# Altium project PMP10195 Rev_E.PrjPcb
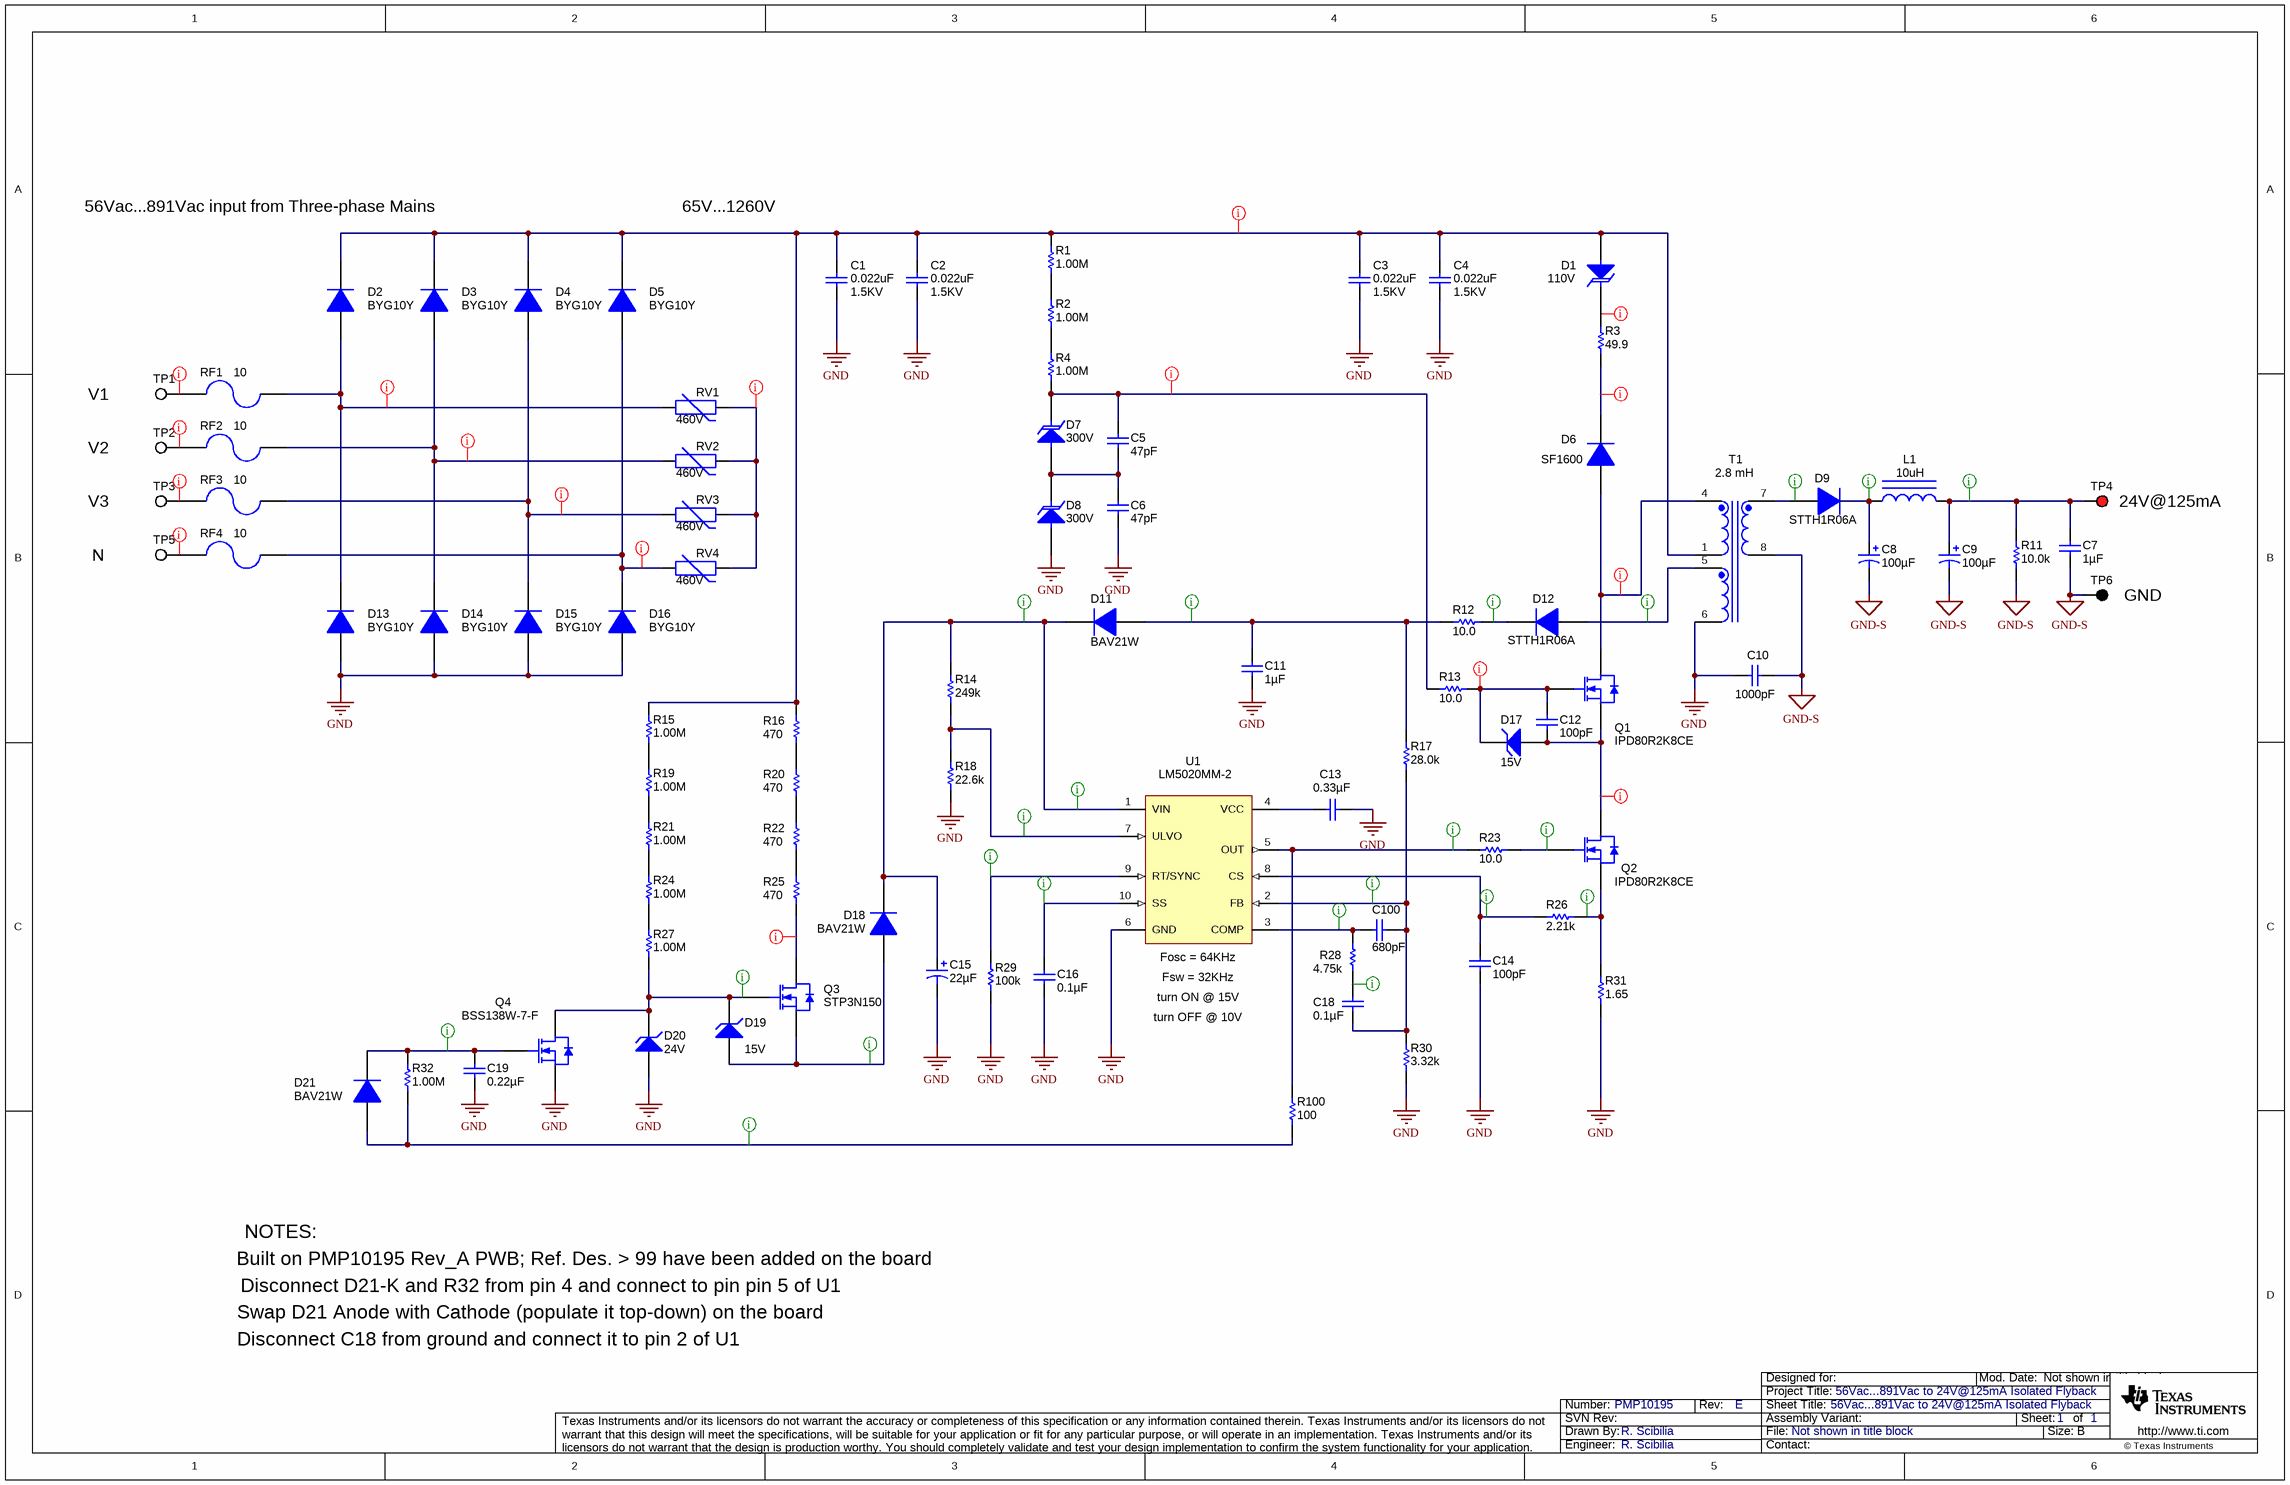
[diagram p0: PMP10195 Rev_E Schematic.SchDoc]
SCH_Rev: E; PRJ_Title: 56Vac...891Vac to 24V@125mA Isolated Flyback; PRJ_Number: PMP10195; PRJ_Engineer: R. Scibilia; PCB_Rev: A
1 sheet, 87 parts. Net scope: global (net labels, ports and power ports of the same name join across sheets).
Board file: PMP10195 Rev_A PCB.PcbDoc

## Sheet PMP10195 Rev_E Schematic.SchDoc: 56Vac...891Vac to 24V@125mA Isolated Flyback
size 431 x 279 mm; Date: Not shown in title block; ApprovedBy: Not shown in title block; CheckedBy: Not shown in title block; Author: Not shown in title block; CompanyName: Not shown in title block; DrawnBy: R. Scibilia; Engineer: R. Scibilia; Organization: Not shown in title block; Address1: Not shown in title block; Address2: Not shown in title block; Address3: Not shown in title block; Address4: Not shown in title block; DocumentNumber: 1; Revision: E; SheetNumber: 1; SheetTotal: 1; PageSetup: Record=PageOptions¦CenterHorizontal=True¦CenterVertical=True¦PrintScale=0.62¦XCorrection=1.00¦YCorrection=1.00¦PrintKind=0¦BorderSize=5000000¦LeftOffset=0¦BottomOffset=0¦Orientation=2¦PaperLength=1000¦PaperWidth=1000¦Scale=100¦PaperSource=15¦PrintQuality=600¦MediaType=1¦DitherType=10¦PaperKind=Letter¦PrintScaleMode=1

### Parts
C1  value 0.022uF  VDC_V: 1.5KV  [1210]  (hidden comment: C1210C223KFRACTU)
C2  value 0.022uF  VDC_V: 1.5KV  [1210]  (hidden comment: C1210C223KFRACTU)
C3  value 0.022uF  VDC_V: 1.5KV  [1210]  (hidden comment: C1210C223KFRACTU)
C4  value 0.022uF  VDC_V: 1.5KV  [1210]  (hidden comment: C1210C223KFRACTU)
C5  ValueDisplayed: 47pF  [1206]  (hidden comment: GRM31A7U3A470JW31D)
C6  ValueDisplayed: 47pF  [1206]  (hidden comment: GRM31A7U3A470JW31D)
C7  ValueDisplayed: 1µF  [0805_HV]  (hidden comment: C2012X7R1H105K125AB)
C8  ValueDisplayed: 100µF  [ZLJ_800X1150]  (hidden comment: 50ZLJ100MT78X11.5)
C9  ValueDisplayed: 100µF  [ZLJ_800X1150]  (hidden comment: 50ZLJ100MT78X11.5)
C10  value 1000pF  [1808]  (hidden comment: GA342DR7GF102KW02L)
C11  ValueDisplayed: 1µF  [0603]  (hidden comment: C1608X5R1E105K080AC)
C12  ValueDisplayed: 100pF  [0603]  (hidden comment: C1608C0G1H101J)
C13  ValueDisplayed: 0.33µF  [0603]  (hidden comment: C0603C334K4RACTU)
C14  ValueDisplayed: 100pF  [0603]  (hidden comment: C1608C0G1H101J)
C15  ValueDisplayed: 22µF  [SM_RADIAL_E]  (hidden comment: EEE-FC1H220P)
C16  ValueDisplayed: 0.1µF  [0603]  (hidden comment: C1608X7R1E104K)
C18  ValueDisplayed: 0.1µF  [0603]  (hidden comment: C1608X7R1E104K)
C19  ValueDisplayed: 0.22µF  [0603]  (hidden comment: C1608X7R1C224K)
C100  ValueDisplayed: 680pF  [0603]  (hidden comment: C1608C0G1H681J)
D1  value 110V  [SMA]  (hidden comment: SMAJ110A)
D2  BYG10Y  [SMA]
D3  BYG10Y  [SMA]
D4  BYG10Y  [SMA]
D5  BYG10Y  [SMA]
D6  SF1600  [DO-41]
D7  value 300V  [SMA]  (hidden comment: SMAJ300A)
D8  value 300V  [SMA]  (hidden comment: SMAJ300A)
D9  STTH1R06A  [SMA]
D11  value BAV21W  [SOD-123]  (hidden comment: BAV21W-7-F)
D12  STTH1R06A  [SMA]
D13  BYG10Y  [SMA]
D14  BYG10Y  [SMA]
D15  BYG10Y  [SMA]
D16  BYG10Y  [SMA]
D17  value 15V  [sod-323]  (hidden comment: MMSZ5245BS-7-F)
D18  value BAV21W  [SOD-123]  (hidden comment: BAV21W-7-F)
D19  value 15V  [sod-323]  (hidden comment: MMSZ5245BS-7-F)
D20  value 24V  [sod-323]  (hidden comment: MMSZ5252BS-7-F)
D21  value BAV21W  [SOD-123]  (hidden comment: BAV21W-7-F)
L1  value 10uH  [NLC453232T]  (hidden comment: NLC453232T-100K-PF)
Q1  IPD80R2K8CE  [DPAK]
Q2  IPD80R2K8CE  [DPAK]
Q3  STP3N150  [TO-220AB]
Q4  BSS138W-7-F  [SOT-323]
R1  ValueDisplayed: 1.00M  [1210M]  (hidden comment: ERJ14NF1004U)
R2  ValueDisplayed: 1.00M  [1210M]  (hidden comment: ERJ14NF1004U)
R3  ValueDisplayed: 49.9  [0603]  (hidden comment: CRCW060349R9FKEA)
R4  ValueDisplayed: 1.00M  [1210M]  (hidden comment: ERJ14NF1004U)
R11  ValueDisplayed: 10.0k  [0805_HV]  (hidden comment: CRCW080510K0FKEA)
R12  value 10.0  [0603]  (hidden comment: CRCW060310R0FKEA)
R13  value 10.0  [0603]  (hidden comment: CRCW060310R0FKEA)
R14  ValueDisplayed: 249k  [0603]  (hidden comment: CRCW0603249KFKEA)
R15  ValueDisplayed: 1.00M  [1210M]  (hidden comment: ERJ14NF1004U)
R16  ValueDisplayed: 470  [2010]  (hidden comment: CRCW2010470RJNEF)
R17  ValueDisplayed: 28.0k  [0603]  (hidden comment: CRCW060328K0FKEA)
R18  ValueDisplayed: 22.6k  [0603]  (hidden comment: CRCW060322K6FKEA)
R19  ValueDisplayed: 1.00M  [1210M]  (hidden comment: ERJ14NF1004U)
R20  ValueDisplayed: 470  [2010]  (hidden comment: CRCW2010470RJNEF)
R21  ValueDisplayed: 1.00M  [1210M]  (hidden comment: ERJ14NF1004U)
R22  ValueDisplayed: 470  [2010]  (hidden comment: CRCW2010470RJNEF)
R23  value 10.0  [0603]  (hidden comment: CRCW060310R0FKEA)
R24  ValueDisplayed: 1.00M  [1210M]  (hidden comment: ERJ14NF1004U)
R25  ValueDisplayed: 470  [2010]  (hidden comment: CRCW2010470RJNEF)
R26  ValueDisplayed: 2.21k  [0603]  (hidden comment: CRCW06032K21FKEA)
R27  ValueDisplayed: 1.00M  [1210M]  (hidden comment: ERJ14NF1004U)
R28  ValueDisplayed: 4.75k  [0603]  (hidden comment: CRCW06034K75FKEA)
R29  ValueDisplayed: 100k  [0603]  (hidden comment: CRCW0603100KFKEA)
R30  ValueDisplayed: 3.32k  [0603]  (hidden comment: CRCW06033K32FKEA)
R31  ValueDisplayed: 1.65  [0805_HV]  (hidden comment: CRCW08051R65FKEA)
R32  ValueDisplayed: 1.00M  [0603]  (hidden comment: CRCW06031M00FKEA)
R100  ValueDisplayed: 100  [0603]  (hidden comment: CRCW0603100RFKEA)
RF1  value 10  [RESAD1524W55L900D150]  (hidden comment: FKN1WSJR-52-10R)
RF2  value 10  [RESAD1524W55L900D150]  (hidden comment: FKN1WSJR-52-10R)
RF3  value 10  [RESAD1524W55L900D150]  (hidden comment: FKN1WSJR-52-10R)
RF4  value 10  [RESAD1524W55L900D150]  (hidden comment: FKN1WSJR-52-10R)
RV1  value 460V  [VAR_S07K300E2]  (hidden comment: B72205S0461K101)
RV2  value 460V  [VAR_S07K300E2]  (hidden comment: B72205S0461K101)
RV3  value 460V  [VAR_S07K300E2]  (hidden comment: B72205S0461K101)
RV4  value 460V  [VAR_S07K300E2]  (hidden comment: B72205S0461K101)
T1  value 2.8 mH  [GCI_EFD15R150-S525]  (hidden comment: EFD15R150-S525)
TP1  5002  [Keystone5002]  (value not drawn)
TP2  5002  [Keystone5002]  (value not drawn)
TP3  5002  [Keystone5002]  (value not drawn)
TP4  5000  [Keystone5000]  (value not drawn)
TP5  5002  [Keystone5002]  (value not drawn)
TP6  5001  [Keystone5001]  (value not drawn)
U1  LM5020MM-2  [MUB10A_N]

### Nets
GND: C1.2 C2.2 C3.2 C4.2 C6.2 C10.2 C11.2 C13.2 C14.2 C15.2(-) C16.2 C19.2 D8.2(A) D13.2(A) D14.2(A) D15.2(A) D16.2(A) D20.2(A) Q4.2(S) R18.1 R29.1 R30.1 R31.1 T1.6 U1.6(GND)
GND-S: C7.2 C8.2(-) C9.2(-) C10.1 R11.1 T1.8 TP6.1
NetC1_1: C1.1 C2.1 C3.1 C4.1 D1.2(A) D2.1(K) D3.1(K) D4.1(K) D5.1(K) R1.2 R15.2 R16.2 T1.1
NetC5_1: C5.1 D7.1(K) R4.1 R13.1
NetC5_2: C5.2 C6.1 D7.2(A) D8.1(K)
NetC7_1: C7.1 C9.1(+) L1.2 R11.2 TP4.1
NetC8_1: C8.1(+) D9.1(K) L1.1
NetC11_1: C11.1 D11.2(A) R12.2 R17.2
NetC12_1: C12.1 D17.1(K) Q1.1(G) R13.2
NetC12_2: C12.2 D17.2(A) Q1.3(S) Q2.4(D)
NetC13_1: C13.1 U1.4(VCC)
NetC14_1: C14.1 R26.1 U1.8(CS)
NetC15_1: C15.1(+) D11.1(K) D18.1(K) R14.2 U1.1(VIN)
NetC16_1: C16.1 U1.10(SS)
NetC18_1: C18.1 R28.1
NetC18_2: C18.2 C100.1 R17.1 R30.2 U1.2(FB)
NetC19_1: C19.1 D21.1(K) Q4.1(G) R32.2
NetC100_2: C100.2 R28.2 U1.3(COMP)
NetD1_1: D1.1(K) R3.2
NetD2_2: D2.2(A) D13.1(K) RF1.1 RV1.1
NetD3_2: D3.2(A) D14.1(K) RF2.1 RV2.1
NetD4_2: D4.2(A) D15.1(K) RF3.1 RV3.1
NetD5_2: D5.2(A) D16.1(K) RF4.1 RV4.1
NetD6_1: D6.1(K) R3.1
NetD6_2: D6.2(A) Q1.4(D) T1.4
NetD9_2: D9.2(A) T1.7
NetD12_1: D12.1(K) R12.1
NetD12_2: D12.2(A) T1.5
NetD18_2: D18.2(A) D19.2(A) Q3.3(S)
NetD19_1: D19.1(K) D20.1(K) Q3.1(G) Q4.3(D) R27.1
NetD21_2: D21.2(A) R32.1 R100.1
NetQ2_1: Q2.1(G) R23.2
NetQ2_3: Q2.3(S) R26.2 R31.2
NetQ3_2: Q3.2(D) R25.1
NetR1_1: R1.1 R2.2
NetR2_1: R2.1 R4.2
NetR14_1: R14.1 R18.2 U1.7(ULVO)
NetR15_1: R15.1 R19.2
NetR16_1: R16.1 R20.2
NetR19_1: R19.1 R21.2
NetR20_1: R20.1 R22.2
NetR21_1: R21.1 R24.2
NetR22_1: R22.1 R25.2
NetR23_1: R23.1 R100.2 U1.5(OUT)
NetR24_1: R24.1 R27.2
NetR29_2: R29.2 U1.9(RT/SYNC)
NetRF1_2: RF1.2 TP1.1
NetRF2_2: RF2.2 TP2.1
NetRF3_2: RF3.2 TP3.1
NetRF4_2: RF4.2 TP5.1
NetRV1_2: RV1.2 RV2.2 RV3.2 RV4.2

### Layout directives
rule Clearance Constraint [Clearance = 1mm]: NetC1_1, NetC5_1, NetC12_1, NetC12_2, NetD1_1, NetD2_2, NetD3_2, NetD4_2, NetD5_2, NetD6_1, NetD6_2, NetQ3_2, NetRF1_2, NetRF2_2, NetRF3_2, NetRF4_2, NetRV1_2
rule Clearance Constraint [Clearance = 0.25mm]: (no net found under the mark), NetC7_1, NetC8_1, NetC11_1, NetC14_1, NetC15_1, NetC16_1, NetC18_1, NetC18_2, NetC19_1, NetC100_2, NetD12_1, NetD12_2, NetD18_2, NetD19_1, NetD21_2, NetQ2_1, NetQ2_3, NetR14_1, NetR23_1, NetR29_2

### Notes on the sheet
- 56Vac...891Vac input from Three-phase Mains
- 65V...1260V
- V1
- V2
- V3
- (near TP4) 24V@125mA
- N
- (near TP6) GND
- (near U1) Fosc = 64KHz
- (near U1) Fsw = 32KHz
- turn ON @ 15V
- turn OFF @ 10V
- NOTES:
- Disconnect D21-K and R32 from pin 4 and connect to pin pin 5 of U1
- Built on PMP10195 Rev_A PWB; Ref. Des. > 99 have been added on the board
- Disconnect C18 from ground and connect it to pin 2 of U1
- Swap D21 Anode with Cathode (populate it top-down) on the board

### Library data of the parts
C1-C4 = VJ1210Y473KXGAT5Z: CAP, CERM, 0.022uF, 1500V, +/-10%, X7R, 1210; Manufacturer: Kemet; Polarized: N; CompType: Capacitor; ValueDisplayed: 0.056µF; U/M: EA; Cap_F: 0.000000047; Tolerance_%: 10; Value1: Unknown; Value2: 1000V; TaMin_C: -55; TaMax_C: 125
C5 C6 = GRM31A7U3A470JW31D: CAP, CERM, 47 pF, 1000 V, +/- 5%, U2J, 1206; Manufacturer: MuRata; Polarized: N; CompType: Capacitor; Value: 47pF; U/M: EA; Cap_F: 0.000000000047; Tolerance_%: 5; Value1: Unknown; VDC_V: 1000; Value2: 1000V; TaMin_C: -55; TaMax_C: 125
C7 = C2012X7R1H105K125AB: CAP, CERM, 1 µF, 50 V, +/- 10%, X7R, 0805; Manufacturer: TDK; Polarized: N; CompType: Capacitor; Value: 1uF; U/M: EA; Cap_F: 0.000001; Tolerance_%: 10; Value1: Unknown; VDC_V: 50; Value2: 50V; TaMin_C: -55; TaMax_C: 125; Cap_Case: 0805
C8 C9 = 50ZLJ100MT78X11.5: CAP, AL, 100 µF, 50 V, +/- 20%, 0.12 ohm, TH; Manufacturer: Rubycon; Polarized: Y; CompType: Capacitor; Value: 100uF; U/M: EA; Cap_F: 0.0001; Tolerance_%: 20; VDC_V: 50; Value2: 50V; ESR_ohm: 0.12; IRMS_A: 0.95; TaMin_C: -40; TaMax_C: 105; Cap_Case: 8x11.5
C10 = VJ1808Y101KXEAT5Z: CAP, CERM, Safety,1000pF, 250V, +/-10%, X1Y2, 1808; Manufacturer: Vishay-Vitramon; Polarized: N; CompType: Capacitor; U/M: EA; Cap_F: 0.0000000001; Tolerance_%: 10; Value1: Unknown; Value2: 500V; TempCo: X7R; TaMin_C: -55; TaMax_C: 125
C11 = C1608X5R1E105K080AC: CAP, CERM, 1 µF, 25 V, +/- 10%, X5R, 0603; Manufacturer: TDK; Polarized: N; CompType: Capacitor; Value: 1uF; U/M: EA; Cap_F: 0.000001; Tolerance_%: 10; Value1: Unknown; VDC_V: 25; Value2: 25V; TaMin_C: -55; TaMax_C: 85; AEC Category: Q200
C12 = C1608C0G1H101J: CAP, CERM, 100 pF, 50 V, +/- 5%, C0G/NP0, 0603; Manufacturer: TDK; Polarized: N; CompType: Capacitor; Value: 100pF; U/M: EA; Cap_F: 0.0000000001; Tolerance_%: 5; ESR_ohm: 0.1679; Value1: 0.1679 ohm; VDC_V: 50; Value2: 50V; TaMin_C: -55; TaMax_C: 125
C13 = C0603C334K4RACTU: CAP, CERM, 0.33uF, 16V, +/-10%, X7R, 0603; Manufacturer: Kemet; Polarized: N; CompType: Capacitor; U/M: EA; Cap_F: 0.00000033; Tolerance_%: 10; Value1: Unknown; VDC_V: 16; TaMin_C: -55; TaMax_C: 125
C14 = C1608C0G1H101J: CAP, CERM, 100 pF, 50 V, +/- 5%, C0G/NP0, 0603; Manufacturer: TDK; Polarized: N; CompType: Capacitor; Value: 100pF; U/M: EA; Cap_F: 0.0000000001; Tolerance_%: 5; ESR_ohm: 0.1679; Value1: 0.1679 ohm; VDC_V: 50; Value2: 50V; TaMin_C: -55; TaMax_C: 125; AEC Category: Q200
C15 = EEE-FC1H220P: CAP, AL, 22 µF, 50 V, +/- 20%, 0.7 ohm, SMD; Manufacturer: Panasonic; Polarized: Y; CompType: Capacitor; Value: 22uF; U/M: EA; Cap_F: 0.000022; Tolerance_%: 20; Value1: 0.7 ohm; VDC_V: 50; Value2: 50V; ESR_ohm: 0.7; IRMS_A: 0.12; TaMin_C: -40; TaMax_C: 105; Cap_Case: E
C16 C18 = C1608X7R1E104K: CAP, CERM, 0.1 µF, 25 V, +/- 10%, X7R, 0603; Manufacturer: TDK; Polarized: N; CompType: Capacitor; Value: 0.1uF; U/M: EA; Cap_F: 0.0000001; Tolerance_%: 10; ESR_ohm: 0.017; Value1: 0.017 ohm; VDC_V: 25; Value2: 25V; TaMin_C: -55; TaMax_C: 125
C19 = C1608X7R1C224K: CAP, CERM, 0.22 µF, 16 V, +/- 10%, X7R, 0603; Manufacturer: TDK; Polarized: N; CompType: Capacitor; Value: 0.22uF; U/M: EA; Cap_F: 0.00000022; Tolerance_%: 10; ESR_ohm: 0.0125; Value1: 0.0125 ohm; VDC_V: 16; Value2: 16V; TaMin_C: -55; TaMax_C: 125
C100 = C1608C0G1H681J: CAP, CERM, 680 pF, 50 V, +/- 5%, C0G/NP0, 0603; Manufacturer: TDK; Polarized: N; CompType: Capacitor; Value: 680pF; U/M: EA; Cap_F: 0.00000000068; Tolerance_%: 5; ESR_ohm: 0.0723; Value1: 0.0723 ohm; VDC_V: 50; Value2: 50V; TaMin_C: -55; TaMax_C: 125; AEC Category: Q200
D1 = SMAJ120A: Diode, TVS, Uni, 110V, 400W, SMA; Manufacturer: MDE Semiconductors; U/M: EA; Power_W: 400; RJA_CperW: 120
D2-D5 D13-D16 = BYG21M-E3/TR: Diode, Fast Rectifier, 1600 V, 1.5 A, SMA; Manufacturer: Vishay-Semiconductor; U/M: EA; Vf_V: 1.6; Value1: 1.5A; Value2: 1.6V; Io_A: 1.5; Vr_V: 1600V; TJmax_C: 150
D6 = UF4007-TP: Diode, Ultrafast, 1600 V, 1 A, TH; Manufacturer: Vishay; U/M: EA; Vf_V: 1.7; Value1: 1A; Value2: 1.7V; Io_A: 1; Vr_V: 1000; TJmax_C: 125; AEC Category: Q101
D7 D8 = SMAJ250A: Diode, TVS, Uni, 300 V, 400 W, SMA; Manufacturer: Littelfuse; U/M: EA; Power_W: 400; Vr_V: 300; Value1: 400W; RJA_CperW: 120
D9 D12 = STTH1R06A: Diode, Ultrafast, 600 V, 1 A, SMA; Manufacturer: STMicroelectronics; U/M: EA; Vf_V: 1; Value1: 1A; Value2: 1V; Vr_V: 600; TJmax_C: 175; RJC_CperW: 30
D11 D18 D21 = BAV21W-7-F: Diode, Switching, 200V, 0.2A, SOD-123; Manufacturer: Diodes Inc.; U/M: EA; Vf_V: 1.25; Io_A: 0.2; TJmax_C: 150
D17 D19 = MMSZ5245BS-7-F: Diode, Zener, 15 V, 200 mW, SOD-323; Manufacturer: Diodes Inc.; SymbolCreator: a0412235; U/M: EA; Power_W: 0.2; Vz_V: 15; Value1: 0.2W; RJA_CperW: 350
D20 = MMSZ5252BS-7-F: Diode, Zener, 24 V, 200 mW, SOD-323; Manufacturer: Diodes Inc.; SymbolCreator: a0412235; U/M: EA; Power_W: 0.2; Vz_V: 24; Value1: 0.2W; RJA_CperW: 350; AEC Category: Q101
L1 = NLC453232T-100K-PF: Inductor, Wirewound, Ferrite, 10 µH, 0.55 A, 0.5 ohm, SMD; Manufacturer: TDK; Ind_H: 10.0E-6; ValueDisplayed: 10µH; Imax_A: 0.55; Irms: 0.55A @ 20C rise; Isat: 0.55A @ 10% inductance drop; DCR_ohm: 0.5; Value1: 0.5 ohm; Value2: 0.55A
Q1 Q2 = IPD30N06S4L-23: MOSFET, N-CH, 800 V, 6 A, DPAK; Manufacturer: Infineon Technologies; Alternate Manufacturer: None; U/M: EA; ChType: N; VdsMax_V: 800; Value1: 2.8 ohm; Rdson45_ohm: 2.8; Value2: 12 nC; QgTyp_nC: 12; Vgs_V: 16; IdsMax_A: 6; AEC Category: Q101
Q3 = STP3N150: MOSFET, N-CH, 1500 V, 2.5 A, TO-220AB; Manufacturer: STMicroelectronics; Alternate Manufacturer: None; U/M: EA; ChType: N; VdsMax_V: 1500; Value1: ? ohm; Value2: 29.3 nC; QgTyp_nC: 29.3; Vgs_V: 30; IdsMax_A: 2.5
Q4 = BSS138W-7-F: MOSFET, N-CH, 50 V, 0.2 A, SOT-323; Manufacturer: Diodes Inc.; Alternate Manufacturer: None; U/M: EA; ChType: N; VdsMax_V: 50; Value1: 3.5 ohm; Rdson45_ohm: 3.5; Value2: ? nC; Vgs_V: 1.5; IdsMax_A: 0.2
R1 R2 R4 R15 R19 R21 R24 R27 = ERJ14NF1004U: RES, 1.00 M, 1%, 0.25 W, 1210; Manufacturer: Panasonic; CompType: Resistor; Value: 1.00Meg; Res_ohm: 1000000; Value_Code: 1M00; Tolerance_%: 1; Power_W: 0.25; Value2: 0.25W; VDC_V: 200; TempCo: 100 ppm/C; EIA_Code: E96; U/M: EA
R3 = CRCW060349R9FKEA: RES, 49.9, 1%, 0.1 W, 0603; Manufacturer: Vishay-Dale; CompType: Resistor; Value: 49.9; Value_Code: 49R9; Tolerance_%: 1; Power_W: 0.1; Value2: 0.1W; VDC_V: 75; TempCo: 100 ppm/C; EIA_Code: E96; U/M: EA; AEC Category: Q200
R11 = CRCW080510K0FKEA: RES, 10.0 k, 1%, 0.125 W, 0805; Manufacturer: Vishay-Dale; CompType: Resistor; Value: 10.0k; Res_ohm: 10000; Value_Code: 10k0; Tolerance_%: 1; Power_W: 0.125; Value2: 0.125W; VDC_V: 150; TempCo: 100 ppm/C; EIA_Code: E96; U/M: EA
R12 R13 R23 = CRCW060310R0FKEA: RES, 10.0 ohm, 1%, 0.1W, 0603; Manufacturer: Vishay-Dale; CompType: Resistor; Res_ohm: 10; Value_Code: 10R0; Tolerance_%: 1; Power_W: 0.1; VDC_V: 75; TempCo: 100 ppm/C; EIA_Code: E96; U/M: EA
R14 = CRCW0603249KFKEA: RES, 249 k, 1%, 0.1 W, 0603; Manufacturer: Vishay-Dale; CompType: Resistor; Value: 249k; Res_ohm: 249000; Tolerance_%: 1; Power_W: 0.1; Value2: 0.1W; VDC_V: 75; TempCo: 100 ppm/C; EIA_Code: E96; U/M: EA
R16 R20 R22 R25 = CRCW2010470RJNEF: RES, 470, 5%, 0.75 W, 2010; Manufacturer: Vishay-Dale; CompType: Resistor; Value: 470; Value_Code: 470R; Tolerance_%: 5; Power_W: 0.75; Value2: 0.75W; VDC_V: 400; TempCo: 200 ppm/C; EIA_Code: E24; U/M: EA
R17 = CRCW060328K0FKEA: RES, 28.0 k, 1%, 0.1 W, 0603; Manufacturer: Vishay-Dale; CompType: Resistor; Value: 28.0k; Res_ohm: 28000; Value_Code: 28k0; Tolerance_%: 1; Power_W: 0.1; Value2: 0.1W; VDC_V: 75; TempCo: 100 ppm/C; EIA_Code: E96; U/M: EA
R18 = CRCW060322K6FKEA: RES, 22.6 k, 1%, 0.1 W, 0603; Manufacturer: Vishay-Dale; CompType: Resistor; Value: 22.6k; Res_ohm: 22600; Value_Code: 22k6; Tolerance_%: 1; Power_W: 0.1; Value2: 0.1W; VDC_V: 75; TempCo: 100 ppm/C; EIA_Code: E96; U/M: EA
R26 = CRCW06032K21FKEA: RES, 2.21 k, 1%, 0.1 W, 0603; Manufacturer: Vishay-Dale; CompType: Resistor; Value: 2.21k; Res_ohm: 2210; Value_Code: 2k21; Tolerance_%: 1; Power_W: 0.1; Value2: 0.1W; VDC_V: 75; TempCo: 100 ppm/C; EIA_Code: E96; U/M: EA; AEC Category: Q200
R28 = CRCW06034K75FKEA: RES, 4.75 k, 1%, 0.1 W, 0603; Manufacturer: Vishay-Dale; CompType: Resistor; Value: 4.75k; Res_ohm: 4750; Value_Code: 4k75; Tolerance_%: 1; Power_W: 0.1; Value2: 0.1W; VDC_V: 75; TempCo: 100 ppm/C; EIA_Code: E96; U/M: EA
R29 = CRCW0603100KFKEA: RES, 100 k, 1%, 0.1 W, 0603; Manufacturer: Vishay-Dale; CompType: Resistor; Value: 100k; Res_ohm: 100000; Tolerance_%: 1; Power_W: 0.1; Value2: 0.1W; VDC_V: 75; TempCo: 100 ppm/C; EIA_Code: E96; U/M: EA; AEC Category: Q200
R30 = CRCW06033K32FKEA: RES, 3.32 k, 1%, 0.1 W, 0603; Manufacturer: Vishay-Dale; CompType: Resistor; Value: 3.32k; Res_ohm: 3320; Value_Code: 3k32; Tolerance_%: 1; Power_W: 0.1; Value2: 0.1W; VDC_V: 75; TempCo: 100 ppm/C; EIA_Code: E96; U/M: EA
R31 = CRCW08051R65FKEA: RES, 1.65, 1%, 0.125 W, 0805; Manufacturer: Vishay-Dale; CompType: Resistor; Value: 1.65; Value_Code: 1R65; Tolerance_%: 1; Power_W: 0.125; Value2: 0.125W; VDC_V: 150; TempCo: 100 ppm/C; EIA_Code: E96; U/M: EA; AEC Category: Q200
R32 = CRCW06031M00FKEA: RES, 1.00 M, 1%, 0.1 W, 0603; Manufacturer: Vishay-Dale; CompType: Resistor; Value: 1.00Meg; Res_ohm: 1000000; Value_Code: 1M00; Tolerance_%: 1; Power_W: 0.1; Value2: 0.1W; VDC_V: 75; TempCo: 100 ppm/C; EIA_Code: E96; U/M: EA; AEC Category: Q200
R100 = CRCW0603100RFKEA: RES, 100, 1%, 0.1 W, 0603; Manufacturer: Vishay-Dale; CompType: Resistor; Value: 100; Value_Code: 100R; Tolerance_%: 1; Power_W: 0.1; Value2: 0.1W; VDC_V: 75; TempCo: 100 ppm/C; EIA_Code: E96; U/M: EA; AEC Category: Q200
RF1-RF4 = FKN1WSJR-52-4R7: RES, 10, 5%, 1 W, Axial resistor; Manufacturer: Yageo America; SymbolCreator: a0412235; ValueDisplayed: 4.7; CompType: Fusible Resistor; Value_Code: 4R70; Tolerance_%: 5; Power_W: 1; Value2: 1W; TempCo: 350 ppm/C; EIA_Code: E24; U/M: EA; AEC Category: Q200
RV1-RV4 = B72207S2301K101: Varistor, 460V, 1.75kA, 7MM Radial, TH; Manufacturer: TDK; SymbolCreator: a0412235
T1 = EFD15R150-S525: Transformer, 2789 uH, TH; Manufacturer: GCI Technologies; SymbolCreator: Altium; DCR_Ohm: 2.5; U/M: EA
TP1-TP3 TP5 = 5002: Test Point, Miniature, White, TH; Manufacturer: Keystone; CompType: Test Point Loop; U/M: EA
TP4 = 5000: Test Point, Miniature, Red, TH; Manufacturer: Keystone; CompType: Test Point Loop; U/M: EA
TP6 = 5001: Test Point, Miniature, Black, TH; Manufacturer: Keystone; CompType: Test Point Loop; U/M: EA
U1 = LM5020MM-2: 100V Current Mode PWM Controller, 10-pin MSOP; Manufacturer: Texas Instruments; PackageTopMarking: ZXTT*SBNB; PowerWise: Y; CompType: Switcher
